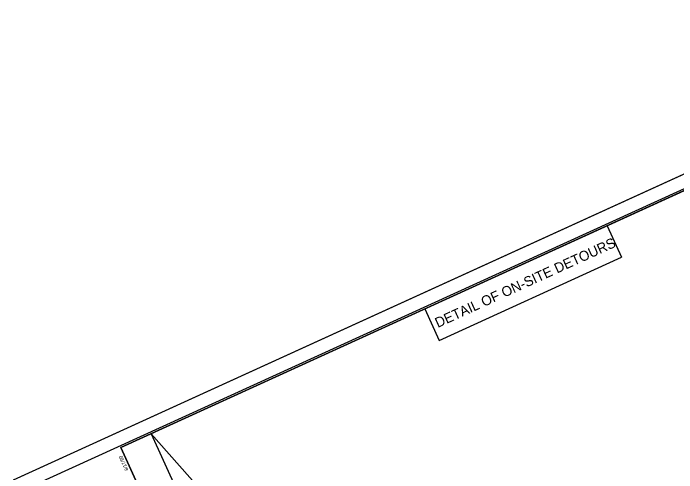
# Model space of a CAD drawing. Extents: x 2249053 to 2251039, y 663030 to 664800.
# Drawn here: x 2249053 to 2250046, y 664038 to 664725 of the extents above; entities that cross this region are included whole.
import ezdxf

# ---------------------------------------------------------------- set-up
doc = ezdxf.new("R2010")
doc.units = 0
for name, color, linetype in [('Prop Dimension', 7, 'Continuous'), ('Sheet Clip Boundary CELL', 7, 'Continuous'), ('Sheet Cutting Line CELL', 7, 'Continuous'), ('Sheet Layout Plan Border', 7, 'Continuous'), ('Sheet Plan CELL', 7, 'Continuous'), ('Sheet Plan Layout CELL', 7, 'Continuous'), ('Sheet Plot Border Inside CELL', 7, 'Continuous'), ('Sheet Plot Border Outside CELL', 7, 'Continuous')]:
    doc.layers.add(name, color=color, linetype=linetype)

msp = doc.modelspace()

# ---------------------------------------------------------------- linework, layer by layer
at = {"layer": 'Sheet Clip Boundary CELL'}
msp.add_lwpolyline([(2249425.27, 663908.72), (2249673.42, 663362.44), (2249698.31, 663307.82), (2249773.57, 663342.12), (2249795.76, 663293.34), (2249720.63, 663258.85), (2249760.8, 663170.69), (2250968.75, 663721.13), (2250621.05, 664484.16), (2250480.7, 664420.21), (2250393.01, 664612.65), (2249259.38, 664096.08)], close=True, dxfattribs=at)
at = {"layer": 'Sheet Cutting Line CELL'}
msp.add_line((2250585, 664724.85), (2249053.06, 664026.77), dxfattribs=at)
at = {"layer": 'Sheet Layout Plan Border'}
msp.add_lwpolyline([(2249694.77, 663140.6), (2250968.75, 663721.13), (2250621.05, 664484.16), (2250448.83, 664405.68), (2250361.13, 664598.13), (2249259.38, 664096.08)], close=True, dxfattribs=at)
at = {"layer": 'Sheet Plan CELL'}
for p, q in [((2249941.84, 664407.06), (2249963.35, 664359.85)), ((2249690.36, 664235.45), (2249963.35, 664359.85)), ((2249668.84, 664282.66), (2249690.36, 664235.45)), ((2249213.88, 664075.35), (2249213.88, 664075.35))]:
    msp.add_line(p, q, dxfattribs=at)
for points in [[(2250578.88, 664697.35), (2249213.88, 664075.35), (2249649.27, 663119.87), (2251014.25, 663741.87)], [(2249649.27, 663119.87), (2249213.87, 664075.31), (2250396.81, 664614.4), (2250459.05, 664477.85), (2250641.08, 664560.79), (2251014.25, 663741.87)]]:
    msp.add_lwpolyline(points, close=True, dxfattribs=at)
at = {"layer": 'Sheet Plan Layout CELL'}
msp.add_lwpolyline([(2249213.87, 664075.31), (2249649.27, 663119.87), (2251014.24, 663741.86), (2250666.54, 664504.89), (2250448.83, 664405.68), (2250361.13, 664598.13)], close=True, dxfattribs=at)
at = {"layer": 'Sheet Plot Border Inside CELL'}
msp.add_lwpolyline([(2249510.65, 663053.94), (2251026.65, 663744.77), (2250589.2, 664704.79), (2249073.18, 664013.96)], close=True, dxfattribs=at)
at = {"layer": 'Sheet Plot Border Outside CELL'}
msp.add_lwpolyline([(2249507.11, 663030.35), (2251039.05, 663728.43), (2250585, 664724.85), (2249053.06, 664026.77)], close=True, dxfattribs=at)

# ---------------------------------------------------------------- texts
at = {"layer": 'Prop Dimension'}
msp.add_text('DETAIL OF ON-SITE DETOURS', height=15, rotation=24.49794, dxfattribs=at).set_placement((2249688.46, 664254.2))
at = {"layer": 'Sheet Plan CELL'}
msp.add_text('8/17/99', height=5.25, rotation=114.49795, dxfattribs=at).set_placement((2249225.55, 664041.95))

doc.saveas('drawing.dxf')
